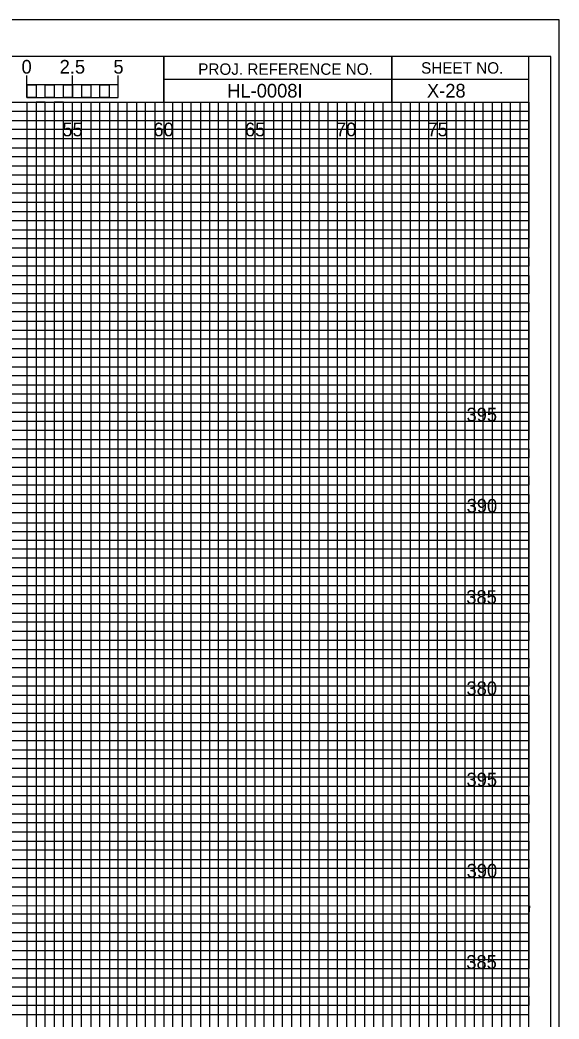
# Model space of a CAD drawing. Extents: x -7 to 162, y -2 to 217.
# Drawn here: x 132.1 to 161.7, y 52.2 to 107 of the extents above; entities that cross this region are included whole.
import ezdxf

# ---------------------------------------------------------------- set-up
doc = ezdxf.new("R2010")
doc.units = 0
for name, color, linetype in [('Exist Cross Section Cell', 7, 'Continuous'), ('Exist XS Center Line Elevation Label', 7, 'Continuous'), ('Exist XS Ground Line', 7, 'Continuous'), ('Prop CMT Pvmt Course 1 CG', 7, 'Continuous'), ('Prop CMT Pvmt Course 2', 7, 'Continuous'), ('Prop CMT Pvmt Course 3', 7, 'Continuous'), ('Prop CMT Pvmt Surface Shoulder', 7, 'Continuous'), ('Prop CMT Shld Paved Course 1', 7, 'Continuous'), ('Prop CMT Shld Paved Course 2', 7, 'Continuous'), ('Prop CMT Shld Paved Course 3', 7, 'Continuous'), ('Prop CMT Slope Grass', 7, 'Continuous'), ('Prop CMT Subgrade Earthwork', 7, 'Continuous'), ('Scratch_Level_3', 7, 'Continuous')]:
    doc.layers.add(name, color=color, linetype=linetype)

msp = doc.modelspace()

# ---------------------------------------------------------------- linework, layer by layer
at = {"layer": 'Prop CMT Pvmt Course 2'}
msp.add_line((0, 102), (160, 102), dxfattribs=at)
for points in [[(0, 101.5), (135, 101.5), (160, 101.5)], [(160, 101), (0, 101)], [(0, 100.5), (160, 100.5)], [(160, 99.5), (0, 99.5)], [(0, 99), (160, 99)], [(160, 98.5), (0, 98.49)], [(0, 98), (160, 98)], [(160, 97), (0, 97)], [(0, 96.5), (160, 96.5), (160, 96), (0, 96)], [(0, 95.5), (160, 95.5), (160, 94.5), (0, 94.5)], [(0, 94), (160, 94), (160, 93.5), (0, 93.5)], [(0, 93), (160, 93), (160, 92), (0, 92)], [(0, 91.5), (160, 91.5), (160, 91), (0, 91)], [(0, 90.5), (160, 90.5), (160, 89.5), (0, 89.5)], [(0, 89), (160, 89), (160, 88.5), (0, 88.5)], [(0, 88), (160, 88), (160, 86.975), (160, 86.5), (160, 86), (0, 86)], [(0, 87), (160, 87), (160, 86.5), (0, 86.5)], [(0, 85.5), (160, 85.5), (160, 84.5), (0, 84.515)], [(0, 84.515), (160, 84.5), (160, 84), (0, 84)], [(0, 83.5), (160, 83.5), (160, 83), (0, 83)], [(0, 82), (160, 82), (160, 81.5), (0, 81.5)], [(0, 81), (160, 81), (160, 80.5), (0, 80.5)], [(-0.035, 79.445), (160, 79.445), (160, 78.94), (-0.035, 78.94)], [(0, 78.5), (160, 78.5), (160, 78), (0, 78)], [(0, 77), (160, 77), (160, 76.5), (0, 76.5)], [(0, 76), (160, 76), (160, 75.5), (0, 75.5)], [(0, 74.5), (160, 74.5), (160, 74), (0, 74)], [(0, 73.5), (160, 73.5), (160, 73), (0, 73)], [(0, 72), (160, 72), (160, 71.5), (0, 71.5)], [(0, 71), (160, 71), (160, 70.5), (0, 70.5)], [(0, 69.5), (160, 69.5), (159.995, 68.99), (0, 69)], [(0, 68.5), (160, 68.5), (160, 68), (0, 68)], [(0, 67), (160, 67), (160, 66.5), (0, 66.5)], [(0, 66), (160, 66), (160, 65.5), (0, 65.5)], [(0, 64.5), (160, 64.5), (160, 64), (0, 64)], [(0, 63.5), (160, 63.5), (160, 63), (0, 63)], [(0, 62), (160, 62), (160, 61.5), (0, 61.5)], [(0, 61), (160, 61), (160, 60.5), (0, 60.5)], [(0, 59.5), (160, 59.5), (160, 59), (0, 59)], [(0, 58.495), (160.035, 58.455), (160, 58), (0, 58)], [(0, 57), (160, 57), (160, 56.5), (0, 56.5)], [(0, 56), (160, 56), (160, 55.5), (0, 55.5)], [(0, 54.5), (160, 54.5), (160, 54), (0, 54)], [(0, 53.5), (160, 53.5), (160, 53), (0, 53)]]:
    msp.add_lwpolyline(points, dxfattribs=at)
at = {"layer": 'Prop CMT Pvmt Course 3'}
for p, q in [((135, 0), (135, 102.5)), ((140, 102.5), (140, 0)), ((145, 0), (145, 102.5)), ((150, 102.5), (150, 0)), ((155, 0), (155, 102.5))]:
    msp.add_line(p, q, dxfattribs=at)
for points in [[(160, 102.5), (160, 95), (0, 95)], [(0, 100), (160, 100)], [(0, 90), (160, 90), (160, 85), (0, 85)], [(0, 80), (160, 80), (160, 75), (0, 75)], [(0, 70), (160, 70), (160, 65), (0, 65)], [(0, 60), (160, 60), (160, 55), (0, 55)]]:
    msp.add_lwpolyline(points, dxfattribs=at)
at = {"layer": 'Prop CMT Shld Paved Course 1'}
msp.add_lwpolyline([(-6.7, -2.5), (161.65, -2.5), (161.65, 107), (-6.7, 107)], close=True, dxfattribs=at)
at = {"layer": 'Prop CMT Shld Paved Course 2'}
msp.add_lwpolyline([(-5.4, -0.5), (161.2, -0.5), (161.2, 105), (-5.4, 105)], close=True, dxfattribs=at)
at = {"layer": 'Prop CMT Shld Paved Course 3'}
for points in [[(127.5, 105), (129.965, 105), (130, 105), (130, 102.5), (132.495, 102.5), (132.495, 0), (137.5, 0), (137.5, 102.5), (140, 102.5)], [(0, 102.5), (137.5, 102.5)], [(0, 92.5), (160, 92.5), (160, 102.5)], [(142.5, 102.5), (142.5, 0), (147.5, 0), (147.5, 102.5)], [(152.5, 102.5), (152.5, 0), (157.5, 0), (157.5, 102.5)], [(160, 97.5), (0, 97.5)], [(0, 82.5), (160, 82.5), (160, 87.5), (0, 87.5)], [(0, 72.5), (160, 72.5), (160, 77.5), (0, 77.5)], [(0, 62.5), (160, 62.5), (160, 67.5), (0, 67.5)], [(0, 52.5), (160, 52.5), (160, 57.5), (0, 57.5)]]:
    msp.add_lwpolyline(points, dxfattribs=at)
at = {"layer": 'Prop CMT Slope Grass'}
for p, q in [((132.5, 102.745), (132.5, 103.95)), ((132.5, 103.45), (132.5, 103.95)), ((135, 102.745), (135, 103.95)), ((137.5, 102.745), (137.5, 103.95)), ((137.5, 103.45), (137.5, 103.95))]:
    msp.add_line(p, q, dxfattribs=at)
for points in [[(137.5, 103.45), (132.5, 103.45), (132.5, 102.745), (137.5, 102.745)], [(132.5, 103.45), (133, 103.45), (133, 102.745), (132.5, 102.745)], [(133.5, 103.45), (134, 103.45), (134, 102.745), (133.5, 102.745)], [(134.5, 103.45), (135, 103.45), (135, 102.745), (134.5, 102.745)], [(135.5, 103.45), (136, 103.45), (136, 102.745), (135.5, 102.745)], [(136.5, 103.45), (137, 103.45), (137, 102.745), (136.5, 102.745)]]:
    msp.add_lwpolyline(points, close=True, dxfattribs=at)
at = {"layer": 'Prop CMT Subgrade Earthwork'}
for p, q in [((133.5, 102.5), (133.005, 102.5)), ((133.005, 102.5), (133.005, 0)), ((133.5, 0), (133.5, 102.5)), ((134.5, 102.5), (134, 102.5)), ((134, 102.5), (134, 0)), ((134.5, 0), (134.5, 102.5))]:
    msp.add_line(p, q, dxfattribs=at)
for points in [[(135, 0), (135.49, 0), (135.49, 102.5), (136, 102.5), (136, 0)], [(136, 0), (136.5, 0), (136.5, 102.5), (137.025, 102.5), (137.025, 0)], [(137.5, 0), (138, 0), (138, 102.5), (138.5, 102.5), (138.5, 0)], [(138.5, 0), (139, 0), (139, 102.5), (139.5, 102.5), (139.5, 0)], [(140, 0), (140.5, 0), (140.5, 102.5)], [(141, 102.5), (141, 0)], [(141, 0), (141.5, 0), (141.5, 102.5)], [(142, 102.5), (142, 0)], [(142.5, 0), (143, 0), (143, 102.5)], [(143.5, 102.5), (143.5, 0)], [(143.5, 0), (144, 0), (144, 102.5)], [(144.5, 102.5), (144.5, 0)], [(145, 0), (145.5, 0), (145.5, 102.5)], [(146, 102.5), (146, 0)], [(146, 0), (146.5, 0), (146.5, 102.5)], [(147, 102.5), (147, 0)], [(147.5, 0), (148, 0), (148, 102.5)], [(148.5, 102.5), (148.5, 0)], [(148.5, 0), (149, 0), (149, 102.5)], [(149.5, 102.5), (149.5, 0)], [(150, 0), (150.5, 0), (150.5, 102.5)], [(151, 102.5), (151, 0)], [(151, 0), (151.5, 0), (151.5, 102.5)], [(152, 102.5), (152, 0)], [(152.5, 0), (153, 0), (153, 102.5)], [(153.5, 102.5), (153.5, 0)], [(153.5, 0), (154, 0), (154, 102.5)], [(154.5, 102.5), (154.5, 0)], [(155, 0), (155.5, 0), (155.5, 102.5)], [(156, 102.5), (156, 0)], [(156, 0), (156.5, 0), (156.5, 102.5)], [(157, 102.5), (157, 0)], [(157.5, 0), (158, 0), (158, 102.5)], [(158.5, 102.5), (158.5, 0)], [(158.5, 0), (159, 0), (159, 102.5)], [(159.5, 102.5), (159.5, 0)]]:
    msp.add_lwpolyline(points, dxfattribs=at)
at = {"layer": 'Scratch_Level_3'}
for p, q in [((152.5, 105), (152.5, 102.5)), ((152.5, 102.5), (152.5, 105)), ((140, 103.75), (140, 102.5)), ((160, 103.745), (140, 103.745)), ((140, 102.5), (160, 102.5))]:
    msp.add_line(p, q, dxfattribs=at)
for points in [[(160, 105), (0, 105), (0, 0), (160, 0)], [(140, 105), (130, 105), (130, 102.5), (140, 102.5)], [(160, 105), (140, 105), (140, 102.5), (160, 102.5)]]:
    msp.add_lwpolyline(points, close=True, dxfattribs=at)

# ---------------------------------------------------------------- texts
at = {"layer": 'Exist Cross Section Cell'}
for s, p in [('55', (134.441, 100.625)), ('60', (139.429, 100.625)), ('65', (144.441, 100.625)), ('70', (149.429, 100.625)), ('75', (154.441, 100.625))]:
    msp.add_text(s, height=0.75, dxfattribs=at).set_placement(p)
at = {"layer": 'Exist XS Center Line Elevation Label'}
msp.add_text('HL-0008I', height=0.75, dxfattribs=at).set_placement((143.474, 102.75))
at = {"layer": 'Exist XS Ground Line'}
msp.add_text('X-28', height=0.75, dxfattribs=at).set_placement((154.415, 102.75))
at = {"layer": 'Prop CMT Pvmt Course 1 CG'}
for s, p in [('2.5', (134.292, 104.06)), ('5', (137.237, 104.06))]:
    msp.add_text(s, height=0.75, dxfattribs=at).set_placement(p)
at = {"layer": 'Prop CMT Pvmt Surface Shoulder'}
for s, p in [('395', (156.582, 85)), ('390', (156.591, 80)), ('385', (156.57, 75)), ('380', (156.579, 70)), ('395', (156.582, 65)), ('390', (156.591, 60)), ('385', (156.57, 55))]:
    msp.add_text(s, height=0.75, dxfattribs=at).set_placement(p)
at = {"layer": 'Prop CMT Slope Grass'}
msp.add_text('0', height=0.75, rotation=360, dxfattribs=at).set_placement((132.205, 104.06))
at = {"layer": 'Scratch_Level_3'}
for s, height, p in [('PROJ. REFERENCE NO.', 0.62499, (141.885, 103.995)), ('SHEET NO.', 0.625, (154.095, 104.06))]:
    msp.add_text(s, height=height, rotation=360, dxfattribs=at).set_placement(p)

doc.saveas('drawing.dxf')
